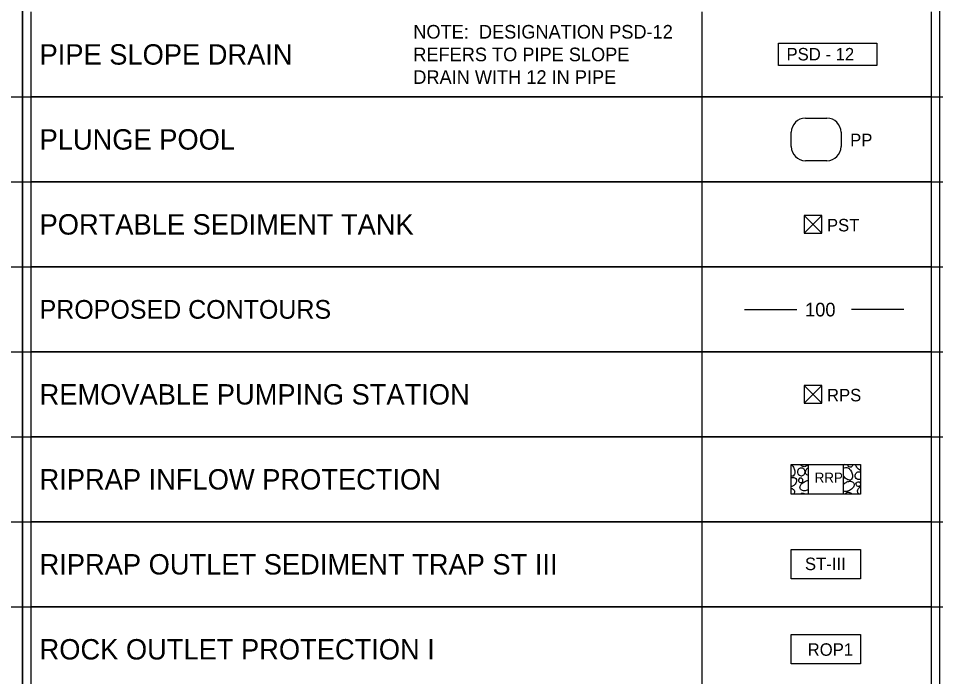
# Model space of a CAD drawing. Extents: x 1.3 to 34, y 0 to 22.5.
# Drawn here: x 7.38 to 12.78, y 11.41 to 15.29 of the extents above; entities that cross this region are included whole.
import ezdxf

# ---------------------------------------------------------------- set-up
doc = ezdxf.new("R2010")
doc.units = 0
for name, color, linetype in [('G-ANNO-SYMB', 7, 'Continuous'), ('G-ANNO-TABL', 7, 'Continuous'), ('G-USER-LINE', 7, 'Continuous')]:
    doc.layers.add(name, color=color, linetype=linetype)

msp = doc.modelspace()

# ---------------------------------------------------------------- linework, layer by layer
at = {"layer": 'G-ANNO-SYMB'}
for p, q in [((12, 14.0228), (12.1044, 14.1272)), ((12, 14.1272), (12.1044, 14.0228)), ((11.65, 13.575), (11.9579, 13.575)), ((12.5872, 13.575), (12.2793, 13.575)), ((12, 13.0228), (12.1044, 13.1272)), ((12, 13.1272), (12.1044, 13.0228)), ((12.0238, 12.6613), (12.0238, 12.4887)), ((12.2312, 12.6613), (12.2312, 12.4887)), ((12.2376, 12.6613), (12.2312, 12.656))]:
    msp.add_line(p, q, dxfattribs=at)
for points in [[(11.85, 15.1407), (12.4294, 15.1407), (12.4294, 15.0093), (11.85, 15.0093)], [(12, 14.0228), (12.1044, 14.0228), (12.1044, 14.1272), (12, 14.1272)], [(12, 13.0228), (12.1044, 13.0228), (12.1044, 13.1272), (12, 13.1272)], [(11.925, 12.6613), (12.3333, 12.6613), (12.3333, 12.4887), (11.925, 12.4887)], [(11.925, 12.1613), (12.3333, 12.1613), (12.3333, 11.9887), (11.925, 11.9887)], [(11.925, 11.6613), (12.3333, 11.6613), (12.3333, 11.4887), (11.925, 11.4887)]]:
    msp.add_lwpolyline(points, close=True, dxfattribs=at)
for points in [[(12.0087, 14.7006), (12.1343, 14.7006)], [(11.925, 14.5331), (11.925, 14.6169)], [(12.218, 14.6169), (12.218, 14.5331)], [(12.1343, 14.4494), (12.0087, 14.4494)]]:
    msp.add_lwpolyline(points, dxfattribs=at)
for centre, start, end in [((12.0087, 14.6169), 90, 180), ((12.1343, 14.6169), 0, 90), ((12.0087, 14.5331), 180, 270), ((12.1343, 14.5331), 270, 0)]:
    msp.add_arc(centre, 0.0837, start, end, dxfattribs=at)
for points in [[(11.9373, 12.6472), (11.9461, 12.6245), (11.9446, 12.6047), (11.9358, 12.5944), (11.925, 12.593)], [(11.9253, 12.6613), (11.9292, 12.6575), (11.938, 12.6458)], [(11.9615, 12.6223), (11.9733, 12.6392), (11.9924, 12.6399), (12.0056, 12.6267), (12.0034, 12.6076), (11.9916, 12.5973), (11.9733, 12.5988), (11.9645, 12.6076), (11.9615, 12.6223)], [(12.0184, 12.6613), (12.0181, 12.6605), (12.0093, 12.6509), (11.9924, 12.6509), (11.9778, 12.6613)], [(12.0238, 12.5986), (12.0232, 12.5988), (12.0107, 12.6076), (12.01, 12.6245), (12.0195, 12.6399), (12.0238, 12.6433)], [(12.2312, 12.6386), (12.2362, 12.6431), (12.2531, 12.6446), (12.2685, 12.635), (12.2773, 12.6233)], [(12.2862, 12.6613), (12.2839, 12.6534), (12.2773, 12.6475), (12.2663, 12.6482), (12.2604, 12.6534), (12.2591, 12.6613)], [(12.3333, 12.6277), (12.3317, 12.6284), (12.3133, 12.6431), (12.3031, 12.6613)], [(11.925, 12.5856), (11.9454, 12.5834), (11.9549, 12.5745), (11.9542, 12.5577), (11.9395, 12.5393), (11.925, 12.5306)], [(11.9667, 12.5709), (11.974, 12.5812), (11.985, 12.5819), (11.9931, 12.5738), (11.9924, 12.5621), (11.985, 12.5562), (11.974, 12.5577), (11.9689, 12.5628), (11.9667, 12.5709)], [(12.2766, 12.6247), (12.2854, 12.602), (12.2839, 12.5821), (12.2751, 12.5719), (12.2582, 12.5726), (12.2391, 12.5873), (12.2312, 12.6011)], [(12.3008, 12.5998), (12.3126, 12.6167), (12.3317, 12.6174), (12.3333, 12.6164)], [(12.3333, 12.576), (12.3309, 12.5748), (12.3126, 12.5763), (12.3038, 12.5851), (12.3008, 12.5998)], [(12.0238, 12.5137), (12.0122, 12.5092), (11.9909, 12.5092), (11.9784, 12.5173), (11.9777, 12.5349), (11.9872, 12.5496), (11.9982, 12.5591)], [(11.9975, 12.5584), (12.0195, 12.5672), (12.0238, 12.5683)], [(12.2421, 12.5542), (12.2641, 12.563), (12.2847, 12.5608), (12.2942, 12.552), (12.2935, 12.5351), (12.2788, 12.5168), (12.256, 12.505), (12.2347, 12.505), (12.2312, 12.5063)], [(12.2312, 12.5449), (12.2318, 12.5454), (12.2428, 12.5542)], [(12.306, 12.5484), (12.3133, 12.5586), (12.3243, 12.5594), (12.3324, 12.5513), (12.3333, 12.549)], [(12.3333, 12.5431), (12.3317, 12.5395), (12.3243, 12.5337), (12.3133, 12.5351), (12.3082, 12.5403), (12.306, 12.5484)], [(12.3249, 12.4887), (12.3177, 12.4947), (12.317, 12.5124), (12.3265, 12.5271), (12.3333, 12.5329)], [(11.925, 12.5221), (11.9299, 12.5202), (11.9432, 12.5062), (11.942, 12.4887)], [(11.9804, 12.4887), (11.9813, 12.4901), (12.0004, 12.4916), (12.0046, 12.4887)], [(12.2449, 12.4887), (12.2502, 12.4962), (12.2693, 12.4977), (12.2795, 12.4887)]]:
    msp.add_spline(points, degree=3, dxfattribs=at)
at = {"layer": 'G-ANNO-TABL'}
for p, q in [((2, 14.825), (18.2, 14.825)), ((2, 14.325), (18.2, 14.325)), ((2, 13.825), (18.2, 13.825)), ((2, 13.325), (18.2, 13.325)), ((2, 12.825), (18.2, 12.825)), ((2, 12.325), (18.2, 12.325)), ((2, 11.825), (18.2, 11.825))]:
    msp.add_line(p, q, dxfattribs=at)
for points in [[(2, 7.825), (7.4, 7.825), (7.4, 19.825), (2, 19.825)], [(7.4, 7.825), (12.8, 7.825), (12.8, 19.825), (7.4, 19.825)]]:
    msp.add_lwpolyline(points, close=True, dxfattribs=at)
at = {"layer": 'G-USER-LINE'}
for p, q in [((7.45, 14.825), (7.45, 15.325)), ((11.4, 14.825), (11.4, 15.325)), ((12.75, 14.825), (12.75, 15.325)), ((7.45, 14.325), (7.45, 14.825)), ((11.4, 14.825), (7.45, 14.825)), ((12.75, 14.825), (11.4, 14.825)), ((11.4, 14.325), (11.4, 14.825)), ((12.75, 14.325), (12.75, 14.825)), ((7.45, 13.825), (7.45, 14.325)), ((11.4, 14.325), (7.45, 14.325)), ((12.75, 14.325), (11.4, 14.325)), ((11.4, 13.825), (11.4, 14.325)), ((12.75, 13.825), (12.75, 14.325)), ((7.45, 13.325), (7.45, 13.825)), ((11.4, 13.825), (7.45, 13.825)), ((12.75, 13.825), (11.4, 13.825)), ((11.4, 13.325), (11.4, 13.825)), ((12.75, 13.325), (12.75, 13.825)), ((7.45, 12.825), (7.45, 13.325)), ((11.4, 13.325), (7.45, 13.325)), ((12.75, 13.325), (11.4, 13.325)), ((11.4, 12.825), (11.4, 13.325)), ((12.75, 12.825), (12.75, 13.325)), ((7.45, 12.325), (7.45, 12.825)), ((11.4, 12.825), (7.45, 12.825)), ((12.75, 12.825), (11.4, 12.825)), ((11.4, 12.325), (11.4, 12.825)), ((12.75, 12.325), (12.75, 12.825)), ((7.45, 11.825), (7.45, 12.325)), ((11.4, 12.325), (7.45, 12.325)), ((12.75, 12.325), (11.4, 12.325)), ((11.4, 11.825), (11.4, 12.325)), ((12.75, 11.825), (12.75, 12.325)), ((7.45, 11.325), (7.45, 11.825)), ((11.4, 11.825), (7.45, 11.825)), ((12.75, 11.825), (11.4, 11.825)), ((11.4, 11.325), (11.4, 11.825)), ((12.75, 11.325), (12.75, 11.825))]:
    msp.add_line(p, q, dxfattribs=at)

# ---------------------------------------------------------------- texts
at = {"layer": 'G-ANNO-SYMB'}
for s, height, p in [('PSD - 12', 0.07344, (11.8969, 15.0397)), ('PP', 0.07344, (12.2716, 14.5351)), ('PST', 0.07344, (12.1351, 14.0338)), ('100', 0.08035, (12.0063, 13.5335)), ('RPS', 0.07344, (12.1351, 13.0338)), ('RRP', 0.05875, (12.063, 12.5556)), ('ST-III', 0.07344, (12.0055, 12.0409)), ('ROP1', 0.07344, (12.0215, 11.5368))]:
    msp.add_text(s, height=height, dxfattribs=at).set_placement(p)
at = {"layer": 'G-ANNO-TABL'}
for s, height, p in [('NOTE:  DESIGNATION PSD-12', 0.08, (9.7, 15.1683)), ('PIPE SLOPE DRAIN', 0.12, (7.5, 15.015)), ('REFERS TO PIPE SLOPE', 0.08, (9.7, 15.035)), ('DRAIN WITH 12 IN PIPE', 0.08, (9.7, 14.9017)), ('PLUNGE POOL', 0.12, (7.5, 14.515)), ('PORTABLE SEDIMENT TANK', 0.12, (7.5, 14.015)), ('PROPOSED CONTOURS', 0.11, (7.5, 13.52)), ('REMOVABLE PUMPING STATION', 0.12, (7.5, 13.015)), ('RIPRAP INFLOW PROTECTION', 0.12, (7.5, 12.515)), ('RIPRAP OUTLET SEDIMENT TRAP ST III', 0.12, (7.5, 12.015)), ('ROCK OUTLET PROTECTION I', 0.12, (7.5, 11.515))]:
    msp.add_text(s, height=height, dxfattribs=at).set_placement(p)

doc.saveas('drawing.dxf')
